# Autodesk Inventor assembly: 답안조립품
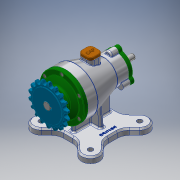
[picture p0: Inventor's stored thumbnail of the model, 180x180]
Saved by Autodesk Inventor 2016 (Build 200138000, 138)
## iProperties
Created: 2018-03
Part Number: 답안조립품
Material: 일반
Document SubType Name: Assembly
Designer: USER
Author: USER
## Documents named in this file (15)
- C:\Users\USER\Desktop\480307V1019\답안조립품.iam
- C:\Users\USER\Desktop\480307V1019\본체.ipt
- C:\Users\USER\Desktop\480307V1019\축.ipt
- C:\Users\USER\Desktop\480307V1019\베어링-6203.ipt
- C:\Users\USER\Desktop\480307V1019\베어링-6200.ipt
- C:\Users\USER\Desktop\480307V1019\앞커버.ipt
- C:\Users\USER\Desktop\480307V1019\오일 실 17 30 8.ipt
- C:\Users\USER\Desktop\480307V1019\볼트 M4 x 12.ipt
- 볼트 M4 x 12.ipt
- C:\Users\USER\Desktop\480307V1019\스프로킷.ipt
- C:\Users\USER\Desktop\480307V1019\키 5 x 5.ipt
- 키 5 x 5.ipt
- C:\Users\USER\Desktop\480307V1019\뒤커버.ipt
- C:\Users\USER\Desktop\480307V1019\오일 실 10 20 7.ipt
- C:\Users\USER\Desktop\480307V1019\마개.ipt
